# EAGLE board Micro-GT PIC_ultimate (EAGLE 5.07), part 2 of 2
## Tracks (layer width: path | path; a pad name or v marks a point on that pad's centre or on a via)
0V  (via drill 0.61)
  Top 0.254: X2.5 46.99,12.7 | 158.75,81.28 X3.2 | 153.67,62.23 153.67,64.77 | 64.77,11.43 X2.G1
  Top 0.508: 91.44,144.78 IC6.8
  Top 0.559: 43.18,27.94 46.99,31.75
  Top 0.61: C13.2 C14.2 86.36,82.55 R66.1 R67.1 88.9,106.68 96.52,106.68 R60.1 | R65.1 91.44,125.73 R63.1 | 92.71,127 R63.1 | R64.1 92.71,127 | R63.1 R61.1 | 92.71,127 92.71,143.51 91.44,144.78 | C3.2 6.35,88.9 6.35,63.5 | IC2.15 55.88,29.21 57.15,29.21 | 59.69,29.21 60.96,29.21 IC4.5 | 59.69,29.21 57.15,29.21 | IC4.14 57.15,38.1 57.15,29.21 | 59.69,29.21 59.69,11.43 55.88,7.62 45.72,7.62 45.72,10.16 | 45.72,10.16 45.72,11.43 46.99,12.7 | R34.2 33.02,29.21 D1.A 31.75,26.67 C12.- 31.75,15.24 IC3.GND | Q6.1 38.1,34.29 38.1,24.13 39.37,22.86 | 39.37,22.86 C2.- | 46.99,31.75 ZX1.31 | 39.37,22.86 39.37,24.13 43.18,27.94 43.18,10.16 45.72,10.16 | v20.32,24.13 20.32,21.59 D3.C | SV26.3 119.38,3.81 R55.A | 153.67,81.28 153.67,62.23 Q4.1
  Top 0.813: R53.1 R52.1 83.82,106.68 R66.1 | ICSP2.3 ICSP1.3 | R54.1 R68.1 | 6.35,63.5 7.62,62.23 SV25.1 DVPP.K DPGC.K | IC1.8 128.27,35.56 120.65,35.56
  Top 1.016: C9.- 8.89,16.51 C1.2 C11.2 C10.2 GND.TP DPGD.K | IC3.GND 29.21,5.08 -.1 | IC1.5 120.65,35.56 120.65,34.29 118.11,34.29 118.11,19.05 R55.A | AN7.1 AN6.1 | AN1.1 AN2.1 AN3.1 AN4.1 | IC4.8 IC4.9 | Q10.E 138.43,151.13 138.43,135.89 139.7,134.62 139.7,129.54 IC7.4 | Q2.1 134.62,19.05
  Top 1.143: AN0.1 76.2,3.81 C7.+
  Top 1.27: SV2.5 SV7.1 | SV7.5 SV8.1 | R56.1 134.62,19.05 R51.1 R57.A | v64.77,3.81 64.77,11.43
  Top 1.676: R77.1 D15.A
  Top 1.778: R78.1 R77.1 120.65,128.27 120.65,134.62 114.3,143.51 Q12.E | AVANTI.K INDIETRO.K 153.67,138.43 153.67,127 158.75,127 X7.2
  Top 2.54: 158.75,81.28 153.67,81.28 153.67,88.9 D8.A D9.A D10.A D11.A 146.05,115.57 D14.A
  Bottom 0.254: 46.99,12.7 X2.5 | 158.75,127 X7.2
  Bottom 0.508: D3.C 26.67,22.86 31.75,22.86 | 31.75,22.86 C12.- | 31.75,22.86 38.1,22.86 C2.-
  Bottom 0.61: R66.1 86.36,106.68 77.47,106.68 RESET.3 | R61.1 R62.1 | C11.2 15.24,24.13 ICSP2.3 v20.32,24.13 | 46.99,12.7 48.26,11.43 X2.G1 | SV26.20 161.29,5.08 154.94,6.35 153.67,8.89 153.67,15.24 148.59,16.51 R57.A | SV26.3 116.84,5.08 110.49,5.08 AN7.1 | Q3.1 Q2.1 Q1.1 152.4,57.15 152.4,59.69 Q4.1 | POWER.K 2.54,11.43 2.54,16.51 C9.-
  Bottom 0.813: R64.1 R60.1 121.92,127 R77.1 | DPGC.K 8.89,40.64 R68.1 | DPGD.K 10.16,38.1 R54.1 | C3.2 5.08,86.36 11.43,86.36 C4.2 | R38.1 8.89,55.88 SV25.1 | IC7.4 137.16,125.73 R78.1
  Bottom 1.016: AN1.1 AN0.1 | AN4.1 AN5.1 AN6.1 | C7.+ 76.2,30.48 69.85,30.48 IC4.8
  Bottom 1.143: AN0.1 v64.77,3.81
  Bottom 1.27: SV1.1 13.97,154.94 26.67,154.94 | 26.67,152.4 SV2.1 | 26.67,152.4 SV1.5 | 54.61,154.94 39.37,154.94 | 26.67,154.94 26.67,152.4 | 39.37,154.94 26.67,154.94 | 39.37,154.94 SV2.5 | 74.93,154.94 R59.1 | 74.93,154.94 68.58,154.94 | IC6.8 91.44,154.94 74.93,154.94 | 54.61,154.94 SV7.5 | 68.58,154.94 54.61,154.94 | 68.58,154.94 SV8.5 | S13.1 S13.2 S13.3 81.28,26.67 C7.+ | R56.1 128.27,15.24 121.92,15.24 R55.A
  Bottom 1.778: 149.86,127 D14.A | IC7.4 149.86,127 | 149.86,127 158.75,127
+5V  (via drill 0.61)
  Top 0.406: 81.28,118.11 78.74,115.57
  Top 0.559: 48.26,68.58 49.53,69.85
  Top 0.61: SV1.3 R12.2 v19.05,147.32 | SV2.3 33.02,151.13 v33.02,147.32 33.02,146.05 34.29,144.78 41.91,144.78 49.53,149.86 | 49.53,149.86 SV7.3 | v63.5,146.05 R42.2 | JP4.1 73.66,100.33 73.66,104.14 74.93,106.68 78.74,110.49 78.74,115.57 | 81.28,118.11 81.28,135.89 82.55,137.16 S10.3 | S10.4 v80.01,144.78 | v52.07,149.86 49.53,149.86 | R55.E 121.92,16.51 121.92,3.81 SV26.4 | C1.1 2.54,21.59 2.54,52.07 SV25.2 | 49.53,69.85 ZX1.32 | v48.26,50.8 48.26,68.58 | v55.88,50.8 55.88,41.91 54.61,40.64 54.61,30.48 IC2.16 48.26,24.13 48.26,20.32 46.99,19.05 C6.- v45.72,15.24 | AN0.3 v73.66,16.51 | v139.7,140.97 139.7,137.16 140.97,135.89 140.97,125.73 139.7,124.46 139.7,85.09 146.05,85.09 146.05,62.23 147.32,60.96 147.32,38.1 142.24,35.56 JP7.2 | IC1.16 111.76,41.91 v113.03,41.91 | IC1.3 v115.57,41.91
  Top 1.016: R55.E 127,22.86 JP6.1 | IC1.4 IC1.3 | AN7.3 AN6.3
  Top 1.27: R42.2 SV8.3
  Bottom 0.406: 24.13,25.4 21.59,22.86 | v73.66,16.51 50.8,16.51 48.26,19.05 C6.-
  Bottom 0.61: v33.02,147.32 v19.05,147.32 | IC6.9 92.71,144.78 v80.01,144.78 69.85,144.78 v63.5,146.05 59.69,146.05 55.88,149.86 v52.07,149.86 | S10.3 S10.4 | JP7.2 140.97,34.29 128.27,34.29 127,35.56 124.46,35.56 | 124.46,35.56 118.11,35.56 IC1.4 | 124.46,35.56 JP6.1 | SV26.4 120.65,5.08 114.3,8.89 AN7.3 | v55.88,50.8 v48.26,50.8 | C1.1 6.35,22.86 21.59,22.86 | 24.13,25.4 41.91,25.4 44.45,27.94 49.53,27.94 IC2.16 | v115.57,41.91 v113.03,41.91
  Bottom 0.813: v139.7,140.97 S10.3
  Bottom 1.016: AN0.3 AN1.3 AN2.3 AN3.3 AN4.3 AN5.3 AN6.3
  Bottom 1.27: IC3.OUT 34.29,15.24 v45.72,15.24
+12V
  Top 0.61: C12.+ 29.21,17.78 26.67,17.78 | 26.67,17.78 IC3.IN | 26.67,17.78 26.67,27.94 24.13,29.21 Q7.E | R79.2 10.16,41.91 R35.2
  Bottom 0.61: C11.1 5.08,24.13 5.08,31.75 6.35,34.29 | 6.35,34.29 6.35,43.18 R35.2 | 6.35,34.29 Q7.E
  Bottom 1.27: IC3.IN 26.67,15.24 20.32,15.24 IC5.OUT
N$1  (via drill 0.61)
  Top 0.813: v137.16,54.61 137.16,58.42 Q2.2
  Bottom 0.61: R9.1 v137.16,54.61
N$2
  Top 0.61: R10.2 106.68,35.56 114.3,35.56 114.3,58.42 Q3.2
N$3  (via drill 0.61)
  Top 0.61: DIS1.5 139.7,55.88 v142.24,55.88
  Bottom 0.61: v142.24,55.88 153.67,55.88 R17.2
N$4
  Top 0.61: POWER.A R79.1
N$5
  Top 1.016: IC1.13 R1.1
N$6
  Top 1.016: IC1.12 R2.1
N$7
  Top 1.016: IC1.11 R3.1
N$8
  Top 1.016: IC1.10 R4.1
N$9
  Top 1.016: IC1.9 R5.1
N$10
  Bottom 0.61: IC1.15 113.03,49.53 120.65,49.53 123.19,52.07 143.51,52.07 144.78,50.8 151.13,50.8 R6.1
N$11
  Top 1.016: IC1.14 R7.1
N$12
  Bottom 0.61: Q1.2 R8.2
N$13  (via drill 0.61)
  Top 0.61: v124.46,50.8 DIS2.5
  Bottom 0.61: R18.2 135.89,50.8 v124.46,50.8
N$14  (via drill 0.61)
  Top 0.61: DIS3.5 110.49,63.5 v110.49,53.34
  Bottom 0.61: v110.49,53.34 144.78,53.34 R19.2
N$15  (via drill 0.61)
  Top 0.813: v148.59,48.26 148.59,60.96 DIS4.5
  Bottom 0.813: R20.2 v148.59,48.26
N$16  (via drill 0.61)
  Top 0.61: v116.84,72.39 DIS2.9
  Top 1.016: DIS4.9 142.24,82.55 129.54,82.55 DIS1.9 v129.54,73.66
  Bottom 0.61: DIS3.9 111.76,72.39 v116.84,72.39 118.11,73.66 v129.54,73.66 | R6.2 161.29,66.04 161.29,83.82 142.24,83.82 DIS4.9
N$17  (via drill 0.61)
  Top 0.61: R1.2 v118.11,76.2 | v134.62,76.2 DIS1.7
  Bottom 0.254: v118.11,76.2 121.92,76.2
  Bottom 0.61: 121.92,76.2 DIS2.7 | DIS3.7 113.03,76.2 v118.11,76.2 v134.62,76.2 152.4,76.2 152.4,82.55 147.32,82.55 DIS4.7
N$18
  Top 0.61: R2.2 120.65,76.2 118.11,78.74 118.11,82.55 | 118.11,82.55 124.46,82.55 DIS2.6 | DIS3.6 111.76,82.55 118.11,82.55
  Bottom 0.61: 137.16,77.47 DIS1.6 | 137.16,77.47 124.46,77.47 DIS2.6 | DIS4.6 149.86,77.47 137.16,77.47
N$19
  Top 0.61: R3.2 121.92,59.69 DIS2.4
  Bottom 0.61: DIS3.4 109.22,62.23 121.92,62.23 | 121.92,62.23 DIS2.4 | 134.62,62.23 DIS1.4 | 121.92,62.23 134.62,62.23 | DIS4.4 147.32,62.23 134.62,62.23
N$20  (via drill 0.61)
  Top 0.61: v104.14,60.96 DIS3.2 | v116.84,60.96 DIS2.2 | R4.2 125.73,57.15 129.54,57.15 DIS1.2 v129.54,68.58
  Bottom 0.61: v104.14,60.96 v116.84,60.96 123.19,60.96 R4.2 | DIS4.2 142.24,68.58 v129.54,68.58
N$21
  Top 0.61: DIS1.1 128.27,63.5 R5.2
  Bottom 0.61: DIS3.1 101.6,67.31 114.3,67.31 | 114.3,67.31 DIS2.1 | DIS4.1 139.7,67.31 127,67.31 | 114.3,67.31 127,67.31 | 127,67.31 DIS1.1
N$22
  Top 0.61: R7.2 115.57,78.74 DIS2.10
  Bottom 1.016: DIS3.10 101.6,82.55 114.3,82.55 | DIS2.10 114.3,82.55 | 127,82.55 DIS1.10 | 114.3,82.55 127,82.55 | DIS4.10 139.7,82.55 127,82.55
N$23  (via drill 0.61)
  Top 0.61: v93.98,88.9 97.79,85.09 97.79,59.69 SV19.1 | IC1.7 119.38,44.45 v119.38,55.88
  Bottom 0.406: IC1.7 128.27,35.56 142.24,35.56 143.51,34.29 143.51,29.21 R51.2
  Bottom 0.61: S26.16 68.58,95.25 87.63,95.25 v93.98,88.9 | v119.38,55.88 110.49,55.88 106.68,58.42 SV19.1
N$24  (via drill 0.61)
  Top 0.61: S13.6 93.98,26.67 v93.98,53.34 | v81.28,58.42 78.74,60.96 v78.74,67.31
  Bottom 0.61: v93.98,53.34 93.98,58.42 v81.28,58.42 | v78.74,67.31 RN1.1
N$25
  Top 1.27: D2.A 17.78,15.24 IC5.GND
N$26  (via drill 0.61)
  Top 0.61: R52.2 v83.82,96.52 | IC1.1 107.95,40.64 v107.95,55.88 107.95,83.82 106.68,86.36 106.68,95.25 v104.14,95.25
  Bottom 0.61: S26.15 64.77,99.06 69.85,99.06 72.39,96.52 v83.82,96.52 | v107.95,55.88 SV19.2 | R52.2 92.71,95.25 v104.14,95.25
N$27  (via drill 0.61)
  Top 0.813: v144.78,73.66 DIS4.8
  Bottom 0.813: Q4.3 146.05,73.66 v144.78,73.66
N$28
  Top 0.254: S2.3 15.24,130.81
  Top 0.61: SV1.4 20.32,151.13 20.32,135.89 17.78,133.35 15.24,133.35 15.24,130.81
  Bottom 0.254: S1.3 7.62,130.81 | 15.24,130.81 S2.3 | 22.86,130.81 S3.3 | 30.48,130.81 S4.3
  Bottom 0.559: 7.62,130.81 8.89,132.08 13.97,132.08 | 13.97,132.08 15.24,130.81 | 21.59,132.08 22.86,130.81 | 13.97,132.08 21.59,132.08 | 30.48,130.81 30.48,132.08 21.59,132.08
N$29
  Top 0.61: S13.4 90.17,22.86 95.25,22.86 RN2.1
N$30  (via drill 0.61)
  Top 0.61: RN3.9 53.34,46.99 v53.34,59.69 | v29.21,60.96 29.21,50.8 RC0.K
  Bottom 0.61: v53.34,59.69 52.07,60.96 v29.21,60.96
N$31  (via drill 0.61)
  Top 0.61: v39.37,50.8 v40.64,45.72
  Bottom 0.61: RC1.K v39.37,50.8 | v40.64,45.72 44.45,45.72 49.53,40.64 RN3.8
N$32
  Bottom 0.61: RC2.K 46.99,45.72 52.07,45.72 RN3.7
N$33
  Top 0.813: R11.2 158.75,63.5 Q4.2
N$34  (via drill 0.61)
  Top 0.61: v24.13,59.69 RB7.K | v62.23,13.97 63.5,15.24 67.31,15.24 v67.31,13.97 | v77.47,13.97 77.47,41.91 RN2.9
  Bottom 0.406: v67.31,13.97 v77.47,13.97
  Bottom 0.61: v24.13,59.69 22.86,60.96 1.27,60.96 1.27,19.05 11.43,19.05 12.7,16.51 46.99,16.51 49.53,13.97 v62.23,13.97
N$35
  Top 0.61: IC2.11 IC4.6
  Bottom 0.61: SV11.2 76.2,31.75 72.39,31.75 69.85,34.29 67.31,34.29 67.31,29.21 63.5,29.21 IC4.6
N$36  (via drill 0.61)
  Top 0.61: IC1.2 109.22,41.91 v109.22,53.34 | v105.41,93.98 105.41,59.69 104.14,58.42 v104.14,53.34
  Bottom 0.61: S26.14 62.23,100.33 72.39,100.33 77.47,102.87 80.01,102.87 R53.2 91.44,93.98 v105.41,93.98 | SV19.3 v104.14,53.34 v109.22,53.34
N$37  (via drill 0.61)
  Top 0.559: 60.96,87.63 v60.96,91.44
  Top 0.61: IC1.6 116.84,44.45 v116.84,50.8 | v50.8,34.29 52.07,34.29 52.07,40.64 53.34,41.91 53.34,44.45 54.61,45.72 54.61,62.23 58.42,66.04 58.42,85.09 60.96,87.63 | v60.96,91.44 60.96,95.25 S26.13 | v102.87,50.8 102.87,58.42 100.33,62.23 v100.33,87.63
  Bottom 0.406: R54.2 22.86,36.83 26.67,36.83 27.94,35.56 29.21,36.83 31.75,34.29 v50.8,34.29
  Bottom 0.61: SV19.4 v102.87,50.8 v116.84,50.8 | v100.33,87.63 76.2,87.63 72.39,91.44 v60.96,91.44
N$38
  Top 0.254: 10.16,137.16 S2.2 10.16,135.89
  Top 0.61: R14.1 10.16,138.43 10.16,137.16 | 10.16,135.89 5.08,130.81 SV30.7
  Bottom 0.559: 25.4,111.76 S11.7
  Bottom 0.61: SV30.7 5.08,111.76 25.4,111.76
N$39  (via drill 0.61)
  Top 0.559: v20.32,95.25 20.32,82.55
  Top 0.61: v39.37,83.82 ZX1.13 | 20.32,82.55 v24.13,82.55 | v20.32,95.25 JP1.2
  Bottom 0.61: v39.37,83.82 38.1,82.55 v24.13,82.55 | JP8.2 1.27,102.87 1.27,96.52 3.81,96.52 5.08,95.25 7.62,95.25 8.89,96.52 12.7,96.52 13.97,95.25 v20.32,95.25
N$40
  Top 0.254: 2.54,137.16 S1.2 2.54,135.89 | 2.54,130.81 S1.1 2.54,129.54
  Top 0.61: R13.1 2.54,139.7 2.54,137.16 | 2.54,130.81 2.54,135.89 | 2.54,129.54 1.27,128.27 1.27,109.22 SV30.8
  Bottom 0.61: SV30.8 2.54,114.3 S11.8
N$41  (via drill 0.61)
  Top 1.016: v36.83,96.52 ZX1.14 | JP2.2 v15.24,96.52
  Bottom 1.016: v15.24,96.52 v36.83,96.52 | JP9.1 JP2.2
N$42  (via drill 0.61)
  Top 0.61: ZX1.9 49.53,93.98 46.99,96.52 46.99,97.79 44.45,102.87 v44.45,104.14 | v5.08,97.79 5.08,91.44 3.81,90.17 3.81,80.01 SV5.2 SV24.2
  Bottom 0.406: v44.45,104.14 25.4,104.14 22.86,101.6 19.05,101.6 16.51,99.06
  Bottom 0.61: 16.51,99.06 6.35,99.06 v5.08,97.79
N$43  (via drill 0.61)
  Top 0.61: v31.75,133.35 31.75,116.84 33.02,115.57 S11.5
  Bottom 0.254: 25.4,137.16 S4.2 25.4,135.89
  Bottom 0.559: 10.16,106.68 SV30.5 | 27.94,109.22 S11.5
  Bottom 0.61: R16.1 16.51,140.97 24.13,140.97 25.4,138.43 25.4,137.16 | 10.16,106.68 22.86,106.68 22.86,109.22 27.94,109.22 | 25.4,135.89 27.94,133.35 v31.75,133.35
N$44  (via drill 0.61)
  Top 0.61: v74.93,58.42 77.47,55.88 RN2.8
  Bottom 0.406: RB6.K 38.1,55.88 39.37,57.15 54.61,57.15 55.88,58.42 v74.93,58.42
N$45  (via drill 0.61)
  Top 0.61: Q5.2 C4.1 v8.89,64.77
  Top 0.813: JP9.2 6.35,101.6 6.35,96.52 Q5.2
  Bottom 0.61: SV6.1 2.54,64.77 v8.89,64.77
N$46
  Top 0.61: Q5.1 2.54,92.71 C3.1 SV5.1
  Top 0.813: Q5.1 JP8.1
N$47  (via drill 0.61)
  Top 0.61: v72.39,85.09 v72.39,101.6 | v52.07,100.33 S26.10
  Top 0.813: v147.32,69.85 152.4,69.85 152.4,49.53 R8.1
  Bottom 0.61: v72.39,85.09 73.66,83.82 82.55,83.82 86.36,80.01 97.79,80.01 107.95,69.85 v147.32,69.85 | R8.1 149.86,49.53 142.24,49.53 135.89,43.18 107.95,43.18 106.68,41.91 102.87,41.91 SV20.2 | v52.07,100.33 53.34,101.6 v72.39,101.6
N$48
  Bottom 0.61: RC3.K RN3.6
N$49
  Top 0.61: RN3.5 RC4.K
N$50  (via drill 0.61)
  Top 0.559: v53.34,86.36 53.34,109.22
  Top 0.61: S26.9 49.53,101.6 50.8,102.87 50.8,109.22 53.34,109.22 | v99.06,86.36 99.06,60.96 101.6,58.42 101.6,48.26 102.87,45.72 102.87,39.37 SV20.1
  Bottom 0.61: v53.34,86.36 54.61,85.09 62.23,85.09 63.5,86.36 v99.06,86.36 | R11.1 157.48,46.99 144.78,46.99 138.43,40.64 104.14,40.64 SV20.1
N$51
  Top 0.61: S25.8 158.75,36.83 157.48,36.83 157.48,46.99 R17.1
N$52
  Bottom 0.406: R18.1 140.97,38.1 143.51,35.56 153.67,35.56 S25.7
N$53
  Top 0.813: Q1.3 140.97,62.23 140.97,72.39 132.08,72.39 DIS1.8
N$54  (via drill 0.61)
  Top 0.813: v127,60.96 125.73,62.23 125.73,73.66 DIS2.8
  Bottom 0.813: Q2.3 133.35,60.96 v127,60.96
N$55  (via drill 0.61)
  Top 0.61: Q3.3 113.03,60.96 v113.03,73.66
  Bottom 0.61: v113.03,73.66 DIS3.8
N$56
  Top 0.61: RN3.4 RC5.K
N$57  (via drill 0.61)
  Top 0.813: S25.6 153.67,35.56 148.59,38.1 v148.59,39.37
  Bottom 0.813: v148.59,39.37 R19.1
N$58
  Bottom 0.61: R20.1 144.78,36.83 157.48,36.83 157.48,30.48 153.67,30.48 S25.5
N$59
  Top 0.61: R21.2 R22.2 R23.2 R24.2 SV2.2
N$60  (via drill 0.61)
  Top 0.254: 53.34,130.81 S7.3
  Top 0.61: SV2.4 35.56,151.13 JP3.2 | v55.88,133.35 54.61,132.08 | 54.61,132.08 53.34,130.81 | 54.61,132.08 v54.61,146.05
  Bottom 0.254: S5.3 38.1,129.54 | 45.72,129.54 S6.3 45.72,130.81 | 60.96,130.81 S8.3
  Bottom 0.457: 58.42,133.35 60.96,130.81
  Bottom 0.559: 45.72,130.81 48.26,133.35
  Bottom 0.61: 38.1,129.54 39.37,127 45.72,128.27 45.72,129.54 | 58.42,133.35 v55.88,133.35 48.26,133.35 | v54.61,146.05 JP3.2
N$61  (via drill 0.61)
  Top 0.254: S5.1 33.02,129.54 | S5.2 33.02,135.89
  Top 0.61: 33.02,143.51 JP3.1 | 33.02,143.51 33.02,137.16 S5.2 | S11.4 35.56,127 33.02,129.54 | 33.02,135.89 33.02,130.81 S5.1 | SV30.4 v12.7,133.35 | 33.02,143.51 30.48,144.78 21.59,144.78 R21.1
  Bottom 0.61: v12.7,133.35 17.78,133.35 20.32,135.89 20.32,139.7 R21.1
N$62  (via drill 0.61)
  Top 0.61: S11.3 36.83,113.03 v36.83,99.06 | v17.78,99.06 17.78,106.68 SV30.3 15.24,115.57 16.51,116.84 16.51,132.08 20.32,132.08 22.86,134.62 27.94,134.62 27.94,138.43 R22.1 v29.21,142.24 | v40.64,142.24 40.64,137.16 S6.2
  Bottom 0.61: v17.78,99.06 v36.83,99.06 | v29.21,142.24 v40.64,142.24
N$63  (via drill 0.61)
  Top 0.559: 39.37,123.19 43.18,119.38
  Top 0.61: v17.78,115.57 SV30.2 | v8.89,115.57 8.89,132.08 12.7,135.89 v12.7,140.97 | S11.2 43.18,116.84 43.18,119.38 | 39.37,123.19 v39.37,132.08 35.56,135.89 v35.56,140.97
  Bottom 0.254: 48.26,135.89 S7.2
  Bottom 0.559: 48.26,134.62 45.72,132.08 v39.37,132.08
  Bottom 0.61: v12.7,140.97 12.7,142.24 26.67,142.24 27.94,140.97 | 27.94,140.97 R23.1 | 27.94,140.97 v35.56,140.97 | 48.26,134.62 48.26,135.89
  Bottom 0.813: v8.89,115.57 v17.78,115.57
N$64  (via drill 0.61)
  Top 0.406: 22.86,102.87 21.59,104.14
  Top 0.508: 48.26,111.76 v46.99,113.03
  Top 0.559: 27.94,130.81 31.75,134.62
  Top 0.61: 27.94,130.81 27.94,124.46 24.13,120.65 24.13,115.57 20.32,115.57 SV30.1 21.59,109.22 21.59,104.14 | 31.75,134.62 R24.1 | v48.26,99.06 48.26,111.76 | v22.86,95.25 22.86,102.87 | v55.88,140.97 55.88,137.16 S8.2
  Bottom 0.61: S11.1 44.45,113.03 v46.99,113.03 | v48.26,99.06 46.99,97.79 40.64,97.79 38.1,95.25 v22.86,95.25 | v55.88,140.97 38.1,140.97 36.83,139.7 R24.1
N$65  (via drill 0.61)
  Top 0.61: v49.53,59.69 50.8,60.96 50.8,64.77 49.53,66.04 RN1.9
  Bottom 0.61: RD0.K 27.94,59.69 v49.53,59.69
N$66
  Top 0.61: R13.2 R14.2 R15.2 R16.2 SV1.2
N$67  (via drill 0.61)
  Top 0.61: R15.1 13.97,140.97 17.78,140.97 17.78,137.16 S3.2 | v22.86,113.03 v22.86,110.49
  Bottom 0.254: 17.78,135.89 S3.2
  Bottom 0.508: 5.08,134.62 16.51,134.62
  Bottom 0.559: 26.67,110.49 S11.6
  Bottom 0.61: 3.81,106.68 7.62,106.68 SV30.6 | 3.81,106.68 1.27,106.68 1.27,121.92 5.08,121.92 5.08,134.62 | 16.51,134.62 17.78,135.89 | v22.86,110.49 26.67,110.49 | v22.86,113.03 3.81,113.03 3.81,106.68
N$68  (via drill 0.61)
  Top 0.559: 5.08,71.12 SV24.1
  Top 0.61: SV6.2 5.08,71.12
  Top 0.813: v46.99,85.09 ZX1.10
  Bottom 0.61: v46.99,85.09 6.35,85.09 6.35,76.2 8.89,76.2 8.89,66.04 5.08,66.04 SV6.2
N$69  (via drill 0.61)
  Top 0.254: S15.1 2.54,119.38 | 2.54,124.46 S15.2
  Top 0.406: SV29.1 67.31,116.84 66.04,115.57 66.04,111.76 69.85,111.76 69.85,116.84 71.12,118.11 71.12,133.35 69.85,134.62 v69.85,143.51
  Top 0.61: S12.16 52.07,111.76 55.88,111.76 55.88,115.57 58.42,118.11 v58.42,120.65 | 48.26,144.78 41.91,142.24 R25.1 | v48.26,147.32 48.26,144.78 | 2.54,119.38 2.54,124.46 | 48.26,144.78 v50.8,143.51
  Bottom 0.254: S15.2 2.54,125.73
  Bottom 0.61: v58.42,120.65 66.04,120.65 SV29.1 | v48.26,147.32 38.1,147.32 36.83,148.59 1.27,148.59 1.27,125.73 2.54,125.73 | v50.8,143.51 v69.85,143.51
N$70  (via drill 0.61)
  Top 0.61: v60.96,110.49 S12.13 | v74.93,115.57 SV29.4 76.2,120.65 v76.2,138.43
  Bottom 0.254: S18.2 25.4,124.46
  Bottom 0.559: 46.99,134.62 44.45,134.62 43.18,133.35 34.29,133.35 31.75,132.08
  Bottom 0.61: v60.96,110.49 60.96,109.22 74.93,109.22 v74.93,115.57 | 46.99,134.62 R28.1 55.88,139.7 57.15,138.43 59.69,138.43 59.69,140.97 69.85,140.97 71.12,138.43 v76.2,138.43 | 31.75,132.08 31.75,128.27 26.67,127 25.4,124.46
N$71  (via drill 0.61)
  Top 1.016: R30.2 v60.96,147.32
  Top 1.27: R32.2 R31.2 | R29.2 R30.2 SV8.2
  Bottom 1.016: R32.2 68.58,147.32 v60.96,147.32
N$72  (via drill 0.61)
  Top 0.61: SV8.4 64.77,151.13 64.77,147.32 71.12,147.32 71.12,137.16 73.66,134.62 v73.66,115.57
  Bottom 0.254: S19.3 38.1,119.38 | 45.72,119.38 S20.3
  Bottom 0.457: 66.04,118.11 68.58,115.57 | 57.15,120.65 58.42,119.38
  Bottom 0.559: 39.37,120.65 44.45,120.65 53.34,120.65 57.15,120.65
  Bottom 0.61: 38.1,119.38 39.37,120.65 | 44.45,120.65 45.72,119.38 | 68.58,115.57 v73.66,115.57 | 66.04,118.11 60.96,118.11 S22.3 60.96,119.38 58.42,119.38 | 53.34,120.65 S21.3
N$73  (via drill 0.61)
  Top 0.508: 54.61,147.32 55.88,146.05
  Top 0.61: v73.66,110.49 74.93,111.76 74.93,113.03 77.47,115.57 SV29.5 | R29.1 55.88,143.51 55.88,146.05 | 54.61,147.32 53.34,147.32 53.34,139.7 50.8,137.16 v50.8,121.92 | v45.72,114.3 43.18,111.76 39.37,111.76 v39.37,121.92
  Bottom 0.254: 33.02,124.46 S19.2 | S19.1 33.02,119.38
  Bottom 0.406: v73.66,110.49 66.04,110.49 63.5,113.03 63.5,115.57 62.23,116.84 S12.12 57.15,116.84 55.88,115.57 54.61,116.84 53.34,115.57 52.07,116.84 49.53,116.84 46.99,114.3 v45.72,114.3
  Bottom 0.61: 33.02,121.92 v39.37,121.92 v50.8,121.92 | 33.02,121.92 33.02,124.46 | 33.02,119.38 33.02,121.92
N$74  (via drill 0.61)
  Top 0.254: 40.64,124.46 S20.2
  Top 0.61: S12.11 62.23,110.49 71.12,110.49 v71.12,116.84 | v80.01,124.46 SV29.6 | 40.64,124.46 41.91,123.19 v43.18,123.19
  Bottom 0.457: SV29.6 77.47,116.84
  Bottom 0.559: 72.39,130.81 62.23,138.43 62.23,139.7 R30.1 | v43.18,123.19 62.23,123.19
  Bottom 0.61: 77.47,116.84 v71.12,116.84 | 72.39,130.81 76.2,130.81 80.01,128.27 v80.01,124.46 63.5,124.46 62.23,123.19
N$75  (via drill 0.61)
  Top 0.61: S12.10 v64.77,123.19 v64.77,133.35 64.77,138.43 R31.1 | v82.55,123.19 SV29.7 | v58.42,132.08 v59.69,133.35
  Bottom 0.254: S21.2 48.26,125.73
  Bottom 0.559: 50.8,132.08 v58.42,132.08
  Bottom 0.61: v64.77,123.19 v82.55,123.19 | 48.26,125.73 50.8,128.27 50.8,132.08 | v59.69,133.35 v64.77,133.35
N$76  (via drill 0.61)
  Top 0.254: 55.88,124.46 S22.2
  Top 0.61: S12.9 68.58,115.57 v68.58,121.92 R32.1 | v55.88,121.92 55.88,124.46
  Bottom 0.61: SV29.8 82.55,121.92 v68.58,121.92 v55.88,121.92
N$77
  Top 1.27: R26.2 R25.2 R27.2 R28.2 SV7.2
N$78  (via drill 0.61)
  Top 0.406: v45.72,109.22 45.72,113.03 50.8,118.11
  Top 0.559: 45.72,121.92 43.18,124.46
  Top 0.61: R26.1 39.37,134.62 40.64,133.35 43.18,133.35 | 43.18,124.46 43.18,133.35 | 45.72,121.92 50.8,120.65 50.8,118.11 50.8,115.57 S12.15 | v69.85,129.54 SV29.2 | 43.18,133.35 48.26,133.35 v49.53,134.62 | v26.67,121.92 27.94,120.65 27.94,116.84 29.21,115.57 29.21,109.22 v35.56,109.22
  Bottom 0.254: S16.2 10.16,124.46
  Bottom 0.559: v69.85,129.54 66.04,132.08 66.04,134.62 v49.53,134.62
  Bottom 0.61: v35.56,109.22 v45.72,109.22
  Bottom 0.813: 10.16,124.46 12.7,121.92 v26.67,121.92
N$79  (via drill 0.61)
  Top 0.61: S12.14 54.61,127 58.42,128.27 | 58.42,128.27 57.15,132.08 57.15,134.62 58.42,135.89 58.42,137.16 59.69,138.43 59.69,143.51 54.61,148.59 52.07,148.59 52.07,140.97 44.45,140.97 R27.1 | v72.39,125.73 SV29.3 | 58.42,128.27 v62.23,127 | v29.21,134.62 29.21,133.35 22.86,133.35 20.32,130.81 20.32,128.27 17.78,125.73 S17.2
  Bottom 0.559: 64.77,125.73 v72.39,125.73 | v29.21,134.62 41.91,134.62 43.18,135.89
  Bottom 0.61: v62.23,127 64.77,125.73 | 43.18,135.89 43.18,139.7 R27.1
N$80  (via drill 0.61)
  Top 0.508: 53.34,71.12 54.61,69.85 RN1.8
  Top 0.61: v38.1,62.23 v38.1,69.85 | v48.26,69.85 v48.26,85.09 | v50.8,85.09 53.34,82.55 53.34,71.12
  Bottom 0.61: RD1.K v38.1,62.23 | v38.1,69.85 v48.26,69.85 | v48.26,85.09 v50.8,85.09
N$81  (via drill 0.61)
  Top 0.559: v43.18,83.82 SV16.1
  Top 0.61: v67.31,85.09 ZX1.2
  Top 1.016: SV16.1 S11.16
  Bottom 0.61: v67.31,85.09 66.04,83.82 v43.18,83.82
N$82  (via drill 0.61)
  Top 0.559: 40.64,81.28 40.64,97.79
  Top 0.61: ZX1.3 64.77,83.82 59.69,83.82 v59.69,81.28 | 40.64,81.28 v44.45,81.28 | 40.64,97.79 41.91,99.06 41.91,100.33 SV16.2
  Top 1.016: SV16.2 S11.15
  Bottom 0.61: v44.45,81.28 v59.69,81.28
N$83  (via drill 0.61)
  Top 0.559: v35.56,80.01 v35.56,97.79
  Top 0.61: v55.88,80.01 v55.88,86.36
  Top 1.016: SV16.3 S11.14
  Bottom 0.406: v35.56,97.79 39.37,97.79 39.37,101.6 SV16.3
  Bottom 0.61: ZX1.4 60.96,86.36 v55.88,86.36 | v35.56,80.01 v55.88,80.01
N$84  (via drill 0.61)
  Top 0.61: ZX1.5 59.69,92.71 58.42,93.98 v58.42,109.22 | v45.72,107.95 41.91,109.22 39.37,109.22 39.37,100.33 v38.1,99.06
  Top 1.016: SV16.4 S11.13
  Bottom 0.406: SV16.4 v38.1,99.06
  Bottom 0.61: v58.42,109.22 49.53,109.22 v45.72,107.95
N$85  (via drill 0.61)
  Top 0.61: v46.99,111.76 v46.99,100.33
  Bottom 0.61: S11.12 33.02,111.76 v46.99,111.76 | v46.99,100.33 50.8,100.33 50.8,93.98 52.07,91.44 54.61,91.44 ZX1.6
N$86  (via drill 0.61)
  Top 0.559: 33.02,86.36 SV16.5
  Top 0.61: v34.29,86.36 33.02,86.36
  Top 1.016: SV16.5 S11.11
  Bottom 0.406: 52.07,86.36 ZX1.7
  Bottom 0.61: v34.29,86.36 52.07,86.36
N$87  (via drill 0.61)
  Top 0.254: 72.39,111.76 RESET.2
  Top 0.61: ZX1.1 71.12,90.17 71.12,104.14 72.39,105.41 RESET.1 72.39,106.68 72.39,111.76 | v19.05,143.51 R12.1 | v63.5,144.78 67.31,144.78 67.31,134.62 66.04,133.35 v66.04,116.84
  Bottom 0.254: RESET.2 72.39,111.76
  Bottom 0.61: v19.05,143.51 19.05,144.78 v63.5,144.78 | v66.04,116.84 66.04,111.76 72.39,111.76
N$88  (via drill 0.61)
  Top 0.61: RD2.K v44.45,66.04
  Bottom 0.406: v44.45,66.04 46.99,68.58 48.26,68.58 49.53,69.85 52.07,69.85 RN1.7
N$89
  Bottom 0.406: RD3.K RN1.6
N$90  (via drill 0.61)
  Top 0.61: S11.10 25.4,109.22 24.13,109.22 v24.13,104.14
  Bottom 0.406: v24.13,104.14 22.86,102.87 JP1.1
N$91  (via drill 0.6, 0.61)
  Top 0.406: v15.24,105.41 JP2.1
  Top 0.813: JP2.1 v15.24,105.41
  Bottom 0.813: S11.9 25.4,105.41 v15.24,105.41
  other vias: 25.4,106.68
N$92
  Top 0.61: RD4.K RN1.5
N$93
  Bottom 0.61: RD5.K RN1.4
N$94  (via drill 0.61)
  Top 0.61: v74.93,64.77 RD6.K
  Bottom 0.61: RN1.3 67.31,64.77 v74.93,64.77
N$95  (via drill 0.61)
  Top 0.61: RN1.2 68.58,66.04 v68.58,63.5
  Bottom 0.61: v68.58,63.5 81.28,63.5 RD7.K
N$96  (via drill 0.61)
  Top 0.61: SV18.1 25.4,66.04 RD0.A | v17.78,91.44 10.16,85.09 v10.16,69.85
  Bottom 0.61: ZX1.19 24.13,91.44 v17.78,91.44 | v10.16,69.85 10.16,62.23 RD0.A
N$97  (via drill 0.61)
  Top 0.61: SV7.4 62.23,142.24 62.23,134.62 63.5,133.35 v63.5,111.76 | v34.29,110.49 31.75,110.49 31.75,115.57 30.48,116.84 30.48,118.11 S18.3
  Bottom 0.254: S15.3 7.62,119.38 | 15.24,119.38 S16.3 | 30.48,119.38 S18.3
  Bottom 0.559: 13.97,120.65 22.86,120.65 29.21,120.65
  Bottom 0.61: 7.62,119.38 8.89,120.65 13.97,120.65 15.24,119.38 | v63.5,111.76 54.61,111.76 46.99,110.49 v34.29,110.49 | 29.21,120.65 30.48,119.38 | 22.86,120.65 S17.3
N$98  (via drill 0.61)
  Top 0.61: v33.02,64.77 RD1.A | v17.78,86.36 12.7,81.28 v12.7,64.77
  Bottom 0.61: 26.67,64.77 v33.02,64.77 | 26.67,64.77 SV18.2 | ZX1.20 21.59,86.36 v17.78,86.36 | v12.7,64.77 26.67,64.77
N$99  (via drill 0.61)
  Top 0.61: SV18.3 v29.21,63.5
  Bottom 0.406: SV18.3 26.67,69.85 17.78,69.85 17.78,73.66 ZX1.21
  Bottom 0.61: RD2.A 40.64,62.23 38.1,63.5 v29.21,63.5
N$100  (via drill 0.61)
  Top 0.61: v27.94,69.85 ZX1.22
  Bottom 0.406: 38.1,64.77 34.29,64.77 SV18.4 29.21,69.85 v27.94,69.85
  Bottom 0.61: 38.1,64.77 40.64,63.5 48.26,63.5 RD3.A
N$101  (via drill 0.61)
  Top 0.61: RD4.A 60.96,58.42 60.96,41.91 59.69,40.64 v59.69,35.56 | v50.8,35.56 48.26,35.56 48.26,49.53 50.8,50.8 v50.8,52.07 | v30.48,50.8 31.75,50.8 31.75,57.15 34.29,58.42 SV18.5 34.29,71.12 ZX1.27
  Bottom 0.406: v50.8,52.07 39.37,52.07 36.83,50.8 v30.48,50.8
  Bottom 0.61: v50.8,35.56 v59.69,35.56
N$102  (via drill 0.61)
  Top 0.61: SV18.6 36.83,71.12 ZX1.28 39.37,76.2 v41.91,78.74 | RD5.A 63.5,63.5 v63.5,78.74
  Bottom 0.61: v41.91,78.74 v63.5,78.74
N$103  (via drill 0.61)
  Top 0.61: SV18.7 39.37,71.12 ZX1.29 | RD6.A 71.12,60.96 71.12,38.1 69.85,36.83 v69.85,35.56 | v64.77,71.12 66.04,72.39 v66.04,81.28 | v72.39,81.28 74.93,81.28 74.93,68.58 76.2,67.31 v76.2,60.96
  Bottom 0.61: v69.85,35.56 72.39,35.56 SV11.3 | ZX1.29 41.91,71.12 v64.77,71.12 | v66.04,81.28 v72.39,81.28 | v76.2,60.96 73.66,60.96 RD6.A
N$104  (via drill 0.61)
  Top 0.61: SV18.8 44.45,69.85 ZX1.30 | v34.29,76.2 33.02,74.93 33.02,66.04 31.75,64.77 v31.75,58.42 | v16.51,57.15 16.51,39.37 13.97,36.83 13.97,24.13 11.43,21.59 v11.43,6.35 | v96.52,6.35 96.52,63.5 SV12.3
  Bottom 0.61: RD7.A 80.01,60.96 88.9,60.96 95.25,63.5 SV12.3 | ZX1.30 41.91,76.2 v34.29,76.2 | v31.75,58.42 30.48,57.15 v16.51,57.15 | v11.43,6.35 12.7,1.27 90.17,1.27 91.44,5.08 96.52,5.08 v96.52,6.35
N$105  (via drill 0.61)
  Top 0.61: v80.01,38.1 RN2.7 | v44.45,50.8 RB5.K
  Bottom 0.406: v80.01,38.1 72.39,38.1 68.58,41.91 67.31,40.64 66.04,41.91 64.77,40.64 63.5,41.91 63.5,46.99 55.88,46.99 53.34,49.53 46.99,49.53 45.72,50.8 v44.45,50.8
N$106  (via drill 0.61)
  Top 0.61: v58.42,57.15 v58.42,50.8
  Bottom 0.61: RB4.K 54.61,55.88 55.88,57.15 v58.42,57.15 | v58.42,50.8 59.69,49.53 72.39,49.53 73.66,50.8 82.55,50.8 83.82,49.53 83.82,44.45 RN2.6
N$107  (via drill 0.61)
  Top 0.61: v85.09,50.8 RN2.5
  Bottom 0.61: RB3.K 62.23,54.61 68.58,54.61 69.85,53.34 82.55,53.34 v85.09,50.8
N$108  (via drill 0.61)
  Top 0.61: RB2.K 69.85,55.88 v69.85,52.07
  Bottom 0.406: v69.85,52.07 82.55,52.07 87.63,46.99 RN2.4
N$109  (via drill 0.61)
  Top 0.61: v90.17,57.15 RN2.3
  Bottom 0.61: RB1.K 76.2,57.15 v90.17,57.15
N$110  (via drill 0.61)
  Top 0.61: RN2.2 v92.71,55.88
  Bottom 0.61: v92.71,55.88 RB0.K
N$111  (via drill 0.61)
  Top 0.61: RB7.A 26.67,54.61 SV17.8 | v76.2,76.2 81.28,76.2 81.28,83.82 78.74,86.36 78.74,101.6 v74.93,104.14 | v16.51,19.05 v16.51,38.1 | v33.02,17.78 33.02,6.35 36.83,2.54 68.58,2.54 v68.58,7.62 | v72.39,11.43 v72.39,22.86 | v90.17,30.48 91.44,31.75 91.44,60.96 87.63,64.77 87.63,72.39 v86.36,72.39
  Top 1.016: S26.1 S12.8
  Bottom 0.406: v68.58,7.62 v72.39,11.43
  Bottom 0.61: ZX1.40 72.39,76.2 v76.2,76.2 82.55,76.2 v86.36,72.39 | v74.93,104.14 73.66,102.87 68.58,102.87 S26.1 | SV17.8 25.4,41.91 16.51,41.91 v16.51,38.1 | v16.51,19.05 17.78,17.78 v33.02,17.78 | v72.39,22.86 73.66,24.13 82.55,24.13 88.9,30.48 v90.17,30.48
N$112  (via drill 0.61)
  Top 0.406: 30.48,35.56 29.21,36.83
  Top 0.508: 68.58,86.36 68.58,91.44
  Top 0.61: RB6.A 33.02,50.8 29.21,46.99 SV17.7 29.21,36.83 | 69.85,80.01 69.85,85.09 68.58,86.36 | 69.85,80.01 v69.85,76.2 | 68.58,91.44 69.85,91.44 69.85,99.06 S26.2 | v30.48,15.24 30.48,35.56 | v71.12,11.43 71.12,35.56 73.66,38.1 73.66,80.01 69.85,80.01
  Top 1.016: S26.2 S12.7
  Bottom 0.61: v69.85,76.2 67.31,76.2 ZX1.39 | v30.48,15.24 30.48,10.16 35.56,10.16 38.1,7.62 66.04,7.62 v71.12,11.43
N$113
  Top 1.016: 8.89,26.67 8.89,31.75 7.62,31.75
N$114  (via drill 0.61)
  Top 0.508: 66.04,83.82 66.04,97.79
  Top 0.61: SV17.5 34.29,49.53 36.83,54.61 v36.83,57.15 | v49.53,58.42 RB4.A | 66.04,83.82 68.58,83.82 68.58,71.12 v69.85,71.12 71.12,71.12 71.12,63.5 v68.58,60.96 | 66.04,97.79 S26.4
  Top 1.016: S26.4 S12.5
  Bottom 0.61: v36.83,57.15 38.1,58.42 v49.53,58.42 54.61,58.42 55.88,59.69 60.96,59.69 62.23,60.96 v68.58,60.96 | SV14.1 87.63,71.12 v69.85,71.12
N$115  (via drill 0.61)
  Top 0.559: 58.42,87.63 58.42,92.71
  Top 0.61: RB3.A 55.88,57.15 v55.88,60.96 | v62.23,64.77 60.96,66.04 60.96,72.39 ZX1.36 59.69,80.01 v63.5,80.01 | JP4.2 73.66,87.63 v73.66,82.55 | SV17.4 39.37,40.64 45.72,40.64 v45.72,82.55 | 58.42,87.63 57.15,86.36 v57.15,82.55 v57.15,80.01 | 58.42,92.71 55.88,95.25 55.88,102.87 S26.5
  Top 1.016: S26.5 S12.4
  Bottom 0.61: v55.88,60.96 60.96,60.96 62.23,62.23 v62.23,64.77 | v73.66,82.55 73.66,80.01 v63.5,80.01 v57.15,80.01 | v45.72,82.55 v57.15,82.55
N$116  (via drill 0.61)
  Top 0.559: 48.26,90.17 48.26,86.36 50.8,83.82
  Top 0.61: SV17.3 38.1,44.45 38.1,58.42 40.64,60.96 v40.64,64.77 | v53.34,64.77 v55.88,64.77 55.88,72.39 ZX1.35 57.15,74.93 v55.88,76.2 | RB2.A 64.77,59.69 v60.96,63.5 | v44.45,99.06 45.72,97.79 45.72,92.71 48.26,90.17 | v50.8,76.2 50.8,83.82
  Top 1.016: S26.6 S12.3
  Bottom 0.406: S26.6 52.07,101.6 46.99,101.6 v44.45,99.06
  Bottom 0.61: v60.96,63.5 59.69,64.77 v55.88,64.77 | v55.88,76.2 v50.8,76.2
  Bottom 0.813: v40.64,64.77 v53.34,64.77
N$117  (via drill 0.61)
  Top 0.254: 52.07,102.87 S26.7
  Top 0.559: 54.61,83.82 50.8,87.63 50.8,101.6
  Top 0.61: ZX1.34 54.61,83.82 | 50.8,101.6 52.07,102.87 | v66.04,36.83 67.31,38.1 67.31,40.64 68.58,41.91 68.58,52.07 66.04,54.61 v66.04,57.15 v66.04,71.12 | v81.28,116.84 80.01,115.57 80.01,95.25 85.09,95.25 85.09,66.04 87.63,63.5 87.63,48.26 88.9,46.99 v88.9,36.83
  Top 1.016: S26.7 S12.2
  Bottom 0.508: ZX1.34 57.15,76.2 66.04,76.2 v66.04,71.12
  Bottom 0.61: SV17.2 48.26,36.83 v66.04,36.83 v88.9,36.83 | v66.04,57.15 71.12,57.15 RB1.A
  Bottom 0.813: S24.3 130.81,119.38 125.73,115.57 114.3,115.57 114.3,123.19 87.63,123.19 87.63,116.84 v81.28,116.84
N$118  (via drill 0.61)
  Top 0.559: 30.48,80.01 30.48,90.17
  Top 0.61: SV17.1 43.18,44.45 43.18,63.5 40.64,66.04 40.64,69.85 43.18,72.39 v43.18,77.47 43.18,80.01 40.64,80.01 39.37,78.74 30.48,78.74 30.48,80.01 | v52.07,77.47 ZX1.33 52.07,71.12 v53.34,69.85 | RB0.A 77.47,58.42 v77.47,68.58 82.55,73.66 v82.55,85.09 | v40.64,99.06 39.37,97.79 v39.37,91.44 | 30.48,90.17 v30.48,91.44
  Top 0.813: S24.4 121.92,115.57 v121.92,91.44
  Top 1.016: S26.8 S12.1
  Bottom 0.406: S26.8 48.26,102.87 46.99,102.87 43.18,99.06 v40.64,99.06
  Bottom 0.61: v43.18,77.47 v52.07,77.47 | v77.47,68.58 77.47,69.85 v53.34,69.85 | v121.92,91.44 118.11,85.09 v82.55,85.09 | v30.48,91.44 v39.37,91.44
N$119
  Bottom 0.61: RN3.3 68.58,46.99 73.66,46.99 RC6.K
N$120
  Bottom 0.61: RN3.2 69.85,45.72 73.66,45.72 74.93,46.99 81.28,46.99 RC7.K
N$121  (via drill 0.61)
  Top 0.559: 22.86,52.07 22.86,74.93
  Top 0.61: SV22.1 25.4,40.64 RC0.A 22.86,52.07 | v26.67,86.36 26.67,78.74 22.86,74.93
  Bottom 0.61: ZX1.15 31.75,86.36 v26.67,86.36
N$122  (via drill 0.61)
  Top 0.559: 30.48,68.58 27.94,71.12
  Top 0.61: RC1.A 30.48,45.72 SV22.2 | v31.75,80.01 ZX1.16 | 27.94,71.12 v27.94,80.01 | v30.48,52.07 30.48,68.58
  Bottom 0.61: v27.94,80.01 v31.75,80.01 | v30.48,52.07 29.21,52.07 29.21,48.26 RC1.A
N$123  (via drill 0.61)
  Top 0.61: SV22.3 33.02,39.37 35.56,41.91 35.56,44.45 v36.83,45.72 v36.83,52.07 | ZX1.17 29.21,77.47 30.48,76.2 v30.48,69.85 | v35.56,69.85 35.56,64.77 36.83,63.5 36.83,58.42 34.29,57.15 v34.29,52.07
  Bottom 0.406: RC2.A 39.37,48.26 v36.83,45.72
  Bottom 0.61: v35.56,69.85 v30.48,69.85 | v36.83,52.07 v34.29,52.07
N$124  (via drill 0.61)
  Top 0.508: 25.4,80.01 25.4,87.63
  Top 0.559: 20.32,74.93 25.4,80.01
  Top 0.61: 25.4,87.63 ZX1.18 | v20.32,49.53 20.32,74.93 | v33.02,45.72 33.02,40.64 31.75,39.37 31.75,36.83 33.02,35.56 35.56,35.56 SV22.4
  Bottom 0.406: RC3.A 46.99,48.26 45.72,49.53 43.18,49.53 43.18,46.99 40.64,46.99 38.1,44.45 38.1,38.1 SV22.4
  Bottom 0.61: v20.32,49.53 22.86,49.53 24.13,45.72 v33.02,45.72
N$125  (via drill 0.61)
  Top 0.61: RC4.A 57.15,52.07 v55.88,53.34 | v10.16,52.07 10.16,66.04 SV23.1
  Bottom 0.61: v55.88,53.34 24.13,53.34 22.86,52.07 v10.16,52.07 | ZX1.23 26.67,76.2 17.78,76.2 SV23.1
N$126  (via drill 0.61)
  Top 0.61: RC5.A 64.77,52.07 v63.5,52.07 | v15.24,54.61 13.97,55.88 SV23.2 v13.97,77.47
  Bottom 0.61: v63.5,52.07 60.96,53.34 59.69,53.34 55.88,54.61 v15.24,54.61 | ZX1.24 29.21,77.47 v13.97,77.47
N$127  (via drill 0.61)
  Top 0.508: v49.53,76.2 50.8,74.93
  Top 0.559: 16.51,72.39 21.59,77.47 v21.59,78.74
  Top 0.61: v78.74,49.53 SV11.1 | v31.75,77.47 ZX1.25 | SV23.3 16.51,72.39 | v72.39,50.8 RC6.A | v52.07,52.07 52.07,53.34 50.8,54.61 50.8,58.42 53.34,60.96 53.34,63.5 50.8,66.04 50.8,74.93
  Bottom 0.406: v49.53,76.2 43.18,76.2 39.37,78.74
  Bottom 0.61: RC6.A 73.66,49.53 v78.74,49.53 | 31.75,78.74 v31.75,77.47 | v21.59,78.74 31.75,78.74 | v72.39,50.8 60.96,50.8 59.69,52.07 v52.07,52.07 | 31.75,78.74 39.37,78.74
N$128  (via drill 0.61)
  Top 0.61: v19.05,71.12 SV23.4 17.78,66.04 17.78,33.02 19.05,31.75 19.05,16.51 22.86,16.51 v22.86,5.08 | 81.28,49.53 83.82,52.07 v83.82,63.5 | 81.28,49.53 RC7.A | v78.74,7.62 81.28,7.62 81.28,49.53
  Bottom 0.61: ZX1.26 34.29,71.12 v19.05,71.12 | v83.82,63.5 85.09,64.77 SV12.1 | v22.86,5.08 76.2,5.08 v78.74,7.62
N$129  (via drill 0.61)
  Top 0.61: v85.09,39.37 88.9,34.29 88.9,26.67 S13.5
  Bottom 0.61: RN3.1 73.66,39.37 v85.09,39.37
N$130
  Bottom 0.406: IC2.2 50.8,21.59 C6.+
N$131  (via drill 0.61)
  Top 0.61: IC2.1 49.53,20.32 v49.53,24.13
  Bottom 0.61: v49.53,24.13 C5.+
N$132
  Bottom 0.406: IC2.3 52.07,22.86 44.45,22.86 44.45,26.67 C5.-
N$133  (via drill 0.61)
  Top 0.61: IC2.6 v63.5,22.86
  Bottom 0.61: v63.5,22.86 69.85,22.86 C7.-
N$134
  Bottom 0.406: IC2.4 60.96,21.59 71.12,21.59 C8.+
N$135  (via drill 0.61)
  Top 0.61: v60.96,15.24 IC2.5
  Bottom 0.406: v60.96,15.24 73.66,15.24 77.47,19.05 77.47,21.59 C8.-
N$136  (via drill 0.61)
  Top 0.508: 44.45,27.94 v45.72,29.21
  Top 0.61: v44.45,11.43 44.45,27.94
  Bottom 0.254: 53.34,10.16 X2.7
  Bottom 0.61: IC2.13 55.88,29.21 v45.72,29.21 | v44.45,11.43 45.72,8.89 53.34,8.89 53.34,10.16
N$137  (via drill 0.61)
  Top 0.254: X2.8 50.8,10.16
  Top 0.61: IC2.14 57.15,25.4 v57.15,15.24 | 50.8,10.16 v50.8,15.24
  Bottom 0.61: v50.8,15.24 v57.15,15.24
N$138  (via drill 0.61)
  Top 0.254: 49.53,12.7 X2.4
  Top 0.61: IC2.8 64.77,24.13 60.96,24.13 v60.96,22.86 | v55.88,21.59 54.61,20.32 54.61,15.24 53.34,13.97 53.34,11.43 52.07,11.43 52.07,8.89 49.53,8.89 49.53,12.7
  Bottom 0.61: v60.96,22.86 55.88,22.86 v55.88,21.59
N$139  (via drill 0.61)
  Top 0.61: R33.1 35.56,29.21 v35.56,20.32 | v48.26,17.78 49.53,17.78 52.07,15.24 X2.3
  Bottom 0.61: v35.56,20.32 38.1,17.78 v48.26,17.78
N$140
  Top 0.61: D1.C 41.91,29.21 R34.1 R33.2 41.91,34.29 43.18,35.56 Q6.2
N$141
  Bottom 0.61: DPGD.A 2.54,36.83 2.54,46.99 20.32,46.99 R37.1
N$142  (via drill 0.61)
  Top 0.61: R36.1 R35.1 20.32,41.91 20.32,36.83 24.13,36.83 25.4,35.56 25.4,31.75 v29.21,29.21 | v44.45,30.48 Q6.3
  Bottom 0.61: v44.45,30.48 43.18,29.21 v29.21,29.21
N$143  (via drill 0.61)
  Top 0.61: v22.86,44.45 22.86,39.37 26.67,35.56 Q7.B
  Bottom 0.61: R36.2 12.7,44.45 v22.86,44.45
N$144
  Top 0.61: Q7.C 24.13,39.37 24.13,46.99 R39.1 R38.2
  Bottom 0.61: R37.2 16.51,50.8 R39.1
N$145
  Top 0.61: SV13.3 95.25,81.28 4MHZ.2
  Bottom 1.016: 4MHZ.2 C14.1
N$146
  Bottom 0.406: IC4.3 59.69,27.94 59.69,24.13 66.04,24.13 IC2.9
N$147
  Top 1.016: C10.1 6.35,26.67 6.35,19.05 2.54,19.05 2.54,12.7 C9.+
  Bottom 1.27: +.1 25.4,7.62 20.32,8.89 15.24,8.89 | C9.+ 7.62,8.89 15.24,8.89 | 15.24,8.89 IC5.IN
N$148
  Top 0.61: R39.2 12.7,49.53 ICSP1.1
  Top 0.813: ICSP2.1 ICSP1.1
N$149  (via drill 0.61)
  Top 0.61: 4MHZ.1 93.98,77.47 93.98,76.2 | 93.98,76.2 93.98,69.85 SV14.3 | 93.98,76.2 v91.44,76.2
  Bottom 0.61: v91.44,76.2 C13.1
N$150  (via drill 0.61)
  Top 0.61: IC2.12 62.23,27.94 62.23,38.1 IC4.11 | v92.71,60.96 SV12.2 | v63.5,59.69 62.23,58.42 v62.23,45.72
  Bottom 0.406: v62.23,45.72 60.96,45.72 60.96,41.91 IC4.11
  Bottom 0.61: v92.71,60.96 91.44,59.69 v63.5,59.69
N$151  (via drill 0.6 pad 1.27, 0.61)  (1 unrouted)
  Top 0.61: SV13.1 v90.17,105.41 | v69.85,107.95 68.58,107.95 67.31,109.22 62.23,109.22 S12.6 | v40.64,50.8 41.91,52.07 RB5.A
  Top 1.016: S12.6 S26.3
  Bottom 0.406: SV17.6 35.56,46.99 36.83,46.99 v40.64,50.8 | v88.9,73.66 90.17,73.66 SV13.1 | RB5.A v40.64,55.88
  Bottom 0.559: 87.63,107.95 v69.85,107.95
  Bottom 0.61: v90.17,105.41 87.63,107.95
N$152  (via drill 0.61)
  Top 0.61: DPGC.A 6.35,43.18 v6.35,59.69
  Bottom 0.61: v6.35,59.69 12.7,59.69 15.24,55.88 R40.1
N$153
  Bottom 0.61: DVPP.A 5.08,52.07 6.35,53.34 6.35,58.42 R41.1
N$154  (via drill 0.61)
  Top 0.61: ZX1.37 v62.23,77.47
  Bottom 0.406: v62.23,77.47 63.5,77.47 64.77,78.74 85.09,78.74
  Bottom 0.61: 85.09,78.74 86.36,77.47 93.98,77.47 93.98,68.58 SV14.2
N$155  (via drill 0.61)
  Top 0.61: ZX1.38 v64.77,77.47
  Bottom 0.61: v64.77,77.47 83.82,77.47 86.36,74.93 92.71,74.93 SV13.2
N$156
  Bottom 0.61: D3.A 16.51,21.59 D2.C
N$157  (via drill 0.61)
  Top 0.254: ICSP1.4 20.32,31.75
  Top 0.61: v19.05,58.42 19.05,33.02 20.32,31.75 | IC4.2 46.99,25.4 v46.99,20.32 | v24.13,24.13 21.59,24.13 21.59,25.4 ICSP2.4
  Top 0.813: ICSP2.4 ICSP1.4
  Bottom 0.406: v46.99,20.32 43.18,20.32 39.37,24.13 v24.13,24.13
  Bottom 0.61: IC4.2 54.61,34.29 64.77,34.29 IC4.7 | v19.05,58.42 R41.2
N$158  (via drill 0.61)
  Top 0.559: v69.85,2.54 69.85,20.32
  Top 0.61: R40.2 13.97,53.34 v13.97,39.37 | v20.32,35.56 22.86,33.02 ICSP1.5 | IC4.12 63.5,41.91 64.77,40.64 64.77,25.4 69.85,20.32 | v25.4,3.81 24.13,3.81 24.13,8.89 25.4,10.16 25.4,26.67 ICSP2.5
  Top 0.813: ICSP2.5 ICSP1.5
  Bottom 0.61: v13.97,39.37 15.24,35.56 v20.32,35.56 | v69.85,2.54 34.29,2.54 33.02,3.81 v25.4,3.81
N$159
  Top 0.813: ZX1.12 JP5.1
N$160
  Top 0.813: ZX1.11 JP5.2
N$161
  Top 0.61: AN0.2 72.39,5.08 72.39,2.54 77.47,2.54 77.47,11.43 80.01,13.97 SV15.1
N$162  (via drill 0.61)
  Top 0.508: 60.96,13.97 62.23,15.24
  Top 0.61: v68.58,12.7 68.58,16.51 62.23,16.51 62.23,15.24 | 60.96,13.97 60.96,11.43 55.88,6.35 34.29,6.35 34.29,15.24 36.83,17.78 C2.+ | v27.94,20.32 v27.94,26.67
  Top 0.813: ICSP1.2 ICSP2.2 | v120.65,119.38 120.65,86.36 128.27,86.36 128.27,71.12 130.81,69.85 v130.81,33.02
  Bottom 0.559: 120.65,125.73 85.09,125.73
  Bottom 0.61: 27.94,31.75 24.13,31.75 22.86,33.02 17.78,33.02 ICSP1.2 | 27.94,31.75 IC4.1 | R42.1 67.31,135.89 77.47,135.89 77.47,132.08 85.09,125.73 | v120.65,119.38 120.65,125.73 | v130.81,33.02 123.19,25.4 110.49,25.4 97.79,12.7 v68.58,12.7 | v27.94,26.67 27.94,31.75 | v27.94,20.32 27.94,19.05 33.02,19.05 33.02,20.32 34.29,21.59 C2.+
N$163
  Top 0.61: AN1.2 82.55,6.35 SV15.2
N$164
  Top 0.61: AN2.2 85.09,7.62 SV15.3
N$165
  Top 0.61: AN3.2 87.63,7.62 SV15.4
N$166
  Top 0.406: AN4.2 90.17,10.16
  Top 0.61: 90.17,10.16 SV15.5
N$167  (via drill 0.61)
  Top 0.406: 92.71,8.89 v93.98,7.62
  Top 0.61: 92.71,8.89 SV15.6
  Bottom 0.61: AN5.2 97.79,7.62 v93.98,7.62
N$168
  Top 0.61: AN6.2 101.6,6.35 101.6,1.27 95.25,1.27 SV15.7
N$169
  Top 0.61: AN7.2 106.68,6.35 106.68,7.62 101.6,7.62 101.6,8.89 97.79,13.97 SV15.8
N$170  (via drill 0.61)
  Top 0.61: SV16.6 31.75,100.33 v31.75,93.98
  Bottom 0.61: ZX1.8 48.26,92.71 33.02,92.71 v31.75,93.98 17.78,93.98 15.24,91.44 3.81,91.44 3.81,77.47 SV24.3
N$171  (via drill 0.61)
  Top 0.406: v22.86,104.14 SV16.8
  Top 0.61: v6.35,104.14 1.27,104.14 1.27,71.12 v2.54,71.12
  Bottom 0.61: v6.35,104.14 v22.86,104.14 | v2.54,71.12 7.62,71.12 SV6.3
N$172  (via drill 0.61)
  Top 0.559: v27.94,83.82 SV16.7
  Bottom 0.61: v27.94,83.82 12.7,83.82 SV5.3
N$173  (via drill 0.61)
  Top 0.61: SV25.3 1.27,54.61 1.27,11.43 12.7,1.27 71.12,1.27 71.12,7.62 74.93,7.62 v74.93,15.24
  Bottom 0.508: v74.93,15.24 81.28,21.59 95.25,21.59 101.6,26.67 119.38,26.67 R55.S
N$174
  Top 1.016: SV3.1 S14.1
N$175
  Top 1.016: R56.2 128.27,33.02 JP6.2
N$176
  Bottom 0.61: SV26.5 123.19,5.08 116.84,8.89 116.84,22.86 142.24,22.86 R57.S
N$177
  Top 1.016: SV3.2 S14.2
N$178
  Top 1.016: SV26.18 153.67,7.62 153.67,19.05 R57.E
N$179
  Top 0.508: 88.9,139.7 IC6.6
  Top 0.61: R63.2 88.9,139.7
  Bottom 0.61: S10.1 82.55,135.89 90.17,135.89 R63.2
N$180
  Top 1.016: R58.1 156.21,6.35 SV26.19
N$181
  Bottom 0.61: R58.2 152.4,29.21 148.59,33.02 JP7.1
N$182
  Top 0.813: IC6.11 93.98,142.24 R64.2
  Bottom 0.61: S10.2 83.82,134.62 91.44,134.62 R64.2
N$183
  Top 1.016: SV26.1 SV27.1
N$184
  Top 1.016: SV26.2 SV27.2
N$185
  Bottom 0.61: SV26.6 125.73,5.08 118.11,10.16 SV27.3
N$186
  Bottom 0.61: SV26.7 128.27,5.08 120.65,10.16 SV27.4
N$187
  Top 1.016: SV26.8 130.81,7.62 123.19,7.62 SV27.5
N$188
  Bottom 0.813: SV27.6 132.08,7.62 151.13,7.62 SV26.17
N$189
  Top 1.016: SV26.9 SV28.1
N$190
  Top 1.016: SV26.10 SV28.2
N$191
  Top 1.016: SV26.11 SV28.3
N$192
  Top 1.016: SV26.12 SV28.4
N$193
  Top 1.016: SV26.13 SV28.5
N$194
  Top 1.016: SV26.14 SV28.6
N$195
  Top 1.016: SV26.15 SV28.7
N$196
  Top 1.016: SV26.16 SV28.8
N$197  (via drill 0.61)
  Top 0.508: IC6.2 83.82,144.78 81.28,142.24 81.28,139.7 78.74,137.16 v78.74,116.84
  Top 2.54: D8.C D4.A
  Bottom 0.254: 158.75,86.36 X4.1
  Bottom 0.61: v78.74,116.84 80.01,115.57 90.17,115.57 90.17,120.65 97.79,120.65
  Bottom 1.778: D8.C 133.35,86.36 158.75,86.36 162.56,86.36 162.56,99.06 157.48,99.06 149.86,104.14 133.35,104.14 132.08,105.41 119.38,105.41 97.79,120.65
N$198  (via drill 0.61)
  Top 0.61: IC6.3 85.09,144.78 83.82,143.51 83.82,116.84 85.09,115.57 v85.09,113.03
  Top 2.54: D5.A D9.C
  Bottom 0.254: 158.75,91.44 X4.2
  Bottom 1.016: v85.09,113.03 92.71,105.41 102.87,105.41 106.68,97.79 125.73,97.79 D5.A
  Bottom 1.676: 157.48,92.71 158.75,91.44
  Bottom 1.778: 157.48,92.71 133.35,92.71 D9.C
N$199  (via drill 0.61)
  Top 0.813: IC6.13 95.25,142.24 v95.25,119.38
  Top 2.54: D10.C D6.A
  Bottom 0.254: X5.1 158.75,96.52
  Bottom 1.016: D6.A 125.73,100.33
  Bottom 1.27: v95.25,119.38 105.41,111.76 105.41,106.68 113.03,104.14 116.84,100.33 125.73,100.33
  Bottom 1.778: 158.75,96.52 153.67,96.52 148.59,99.06 133.35,99.06 D10.C
N$200  (via drill 0.61)
  Top 1.27: v101.6,121.92 101.6,135.89 102.87,138.43 102.87,152.4 IC6.14
  Top 2.54: D7.A D11.C
  Bottom 0.254: 158.75,101.6 X5.2
  Bottom 1.27: v101.6,121.92 106.68,118.11 115.57,111.76 121.92,107.95 D7.A
  Bottom 1.778: 158.75,101.6 158.75,111.76 134.62,111.76 D11.C
N$201  (via drill 0.61)
  Top 0.61: v114.3,74.93 110.49,78.74 D4.C
  Top 1.118: IC6.4 86.36,154.94 106.68,154.94 106.68,111.76 D7.C
  Top 2.54: D4.C D5.C D6.C D7.C
  Bottom 0.254: 158.75,76.2 X3.1
  Bottom 1.016: 158.75,76.2 157.48,74.93 v114.3,74.93
N$202  (via drill 0.61)
  Top 1.016: IC6.1 72.39,147.32 S9.4 72.39,138.43 v73.66,137.16
  Bottom 0.61: R61.2 R62.2 v73.66,137.16
N$203
  Top 0.61: S9.3 R59.2
  Bottom 0.61: R60.2 95.25,138.43 80.01,138.43 S9.3
  Bottom 0.813: IC6.15 100.33,143.51 R59.2
N$204
  Top 1.016: SV3.3 S14.3
N$205
  Top 1.016: SV3.4 S14.4
N$206
  Top 0.61: JP10.1 S9.1
N$207
  Top 0.61: JP10.2 S9.2
N$208  (via drill 0.61)
  Top 0.508: IC6.12 96.52,149.86 97.79,149.86 | 99.06,111.76 99.06,149.86
  Top 0.559: 99.06,149.86 97.79,149.86
  Top 0.61: v35.56,40.64 36.83,39.37 36.83,24.13 38.1,22.86 38.1,15.24 35.56,12.7 v35.56,7.62 | v101.6,11.43 104.14,13.97 v104.14,52.07 | v102.87,60.96 102.87,109.22 S14.5 99.06,111.76
  Bottom 0.61: v35.56,40.64 R68.2 | v35.56,7.62 36.83,6.35 69.85,6.35 73.66,11.43 v101.6,11.43 | v104.14,52.07 96.52,52.07 96.52,60.96 v102.87,60.96
N$209  (via drill 0.61)
  Top 0.61: S14.6 v97.79,144.78
  Bottom 0.457: 93.98,144.78 IC6.10
  Bottom 0.508: v97.79,144.78 93.98,144.78
  Bottom 0.61: R67.2 90.17,113.03 95.25,113.03 S14.6
N$210  (via drill 0.61)
  Top 0.61: S14.7 95.25,107.95 92.71,107.95 R66.2 86.36,121.92 85.09,123.19 v85.09,142.24 | v90.17,142.24 IC6.7
  Bottom 0.813: v85.09,142.24 v90.17,142.24
N$211
  Top 0.61: S14.8 R65.2 87.63,119.38 IC6.5
N$212
  Top 0.813: S24.2 134.62,118.11 IC7.3
N$213
  Top 0.813: IC7.8 124.46,134.62 124.46,148.59
  Top 1.27: R76.1 124.46,148.59 R75.1 Q11.C
  Top 1.778: Q9.C 146.05,134.62 D12.C
  Bottom 1.27: 158.75,115.57 137.16,115.57 137.16,124.46 128.27,124.46 125.73,123.19 124.46,130.81 | 124.46,130.81 129.54,132.08 | 129.54,132.08 IC7.8 | D13.C 114.3,130.81 124.46,130.81 | D12.C 143.51,132.08 129.54,132.08
  Bottom 1.778: 158.75,115.57 X7.1
N$214
  Top 0.813: S24.1 133.35,119.38 133.35,128.27 137.16,132.08 IC7.5
N$215
  Top 1.676: D12.A 143.51,124.46 149.86,124.46 | 149.86,124.46 D14.C | 149.86,124.46 162.56,124.46 162.56,154.94 148.59,154.94
  Top 1.778: 148.59,154.94 Q9.E
  Bottom 0.254: 158.75,132.08 X6.1
  Bottom 1.676: Q10.C 134.62,154.94 148.59,154.94 Q9.E
  Bottom 1.778: 158.75,132.08 149.86,132.08 D14.C
N$216
  Top 1.778: Q12.C 111.76,142.24 116.84,135.89 D15.C 116.84,125.73 D13.A
  Bottom 1.676: 125.73,154.94 Q11.E | 125.73,154.94 111.76,154.94 Q12.C | 125.73,154.94 129.54,154.94 129.54,144.78
  Bottom 1.778: 129.54,144.78 158.75,144.78 X6.2
N$217
  Top 1.27: R69.2 Q9.B
N$218
  Top 1.016: R70.2 Q10.B
N$219
  Top 1.016: R71.1 Q11.B
N$220
  Top 1.27: R72.1 Q12.B
N$221  (via drill 0.6)
  Top 0.813: v135.89,142.24 135.89,148.59 R73.1
  Bottom 0.813: v135.89,142.24 INDIETRO.A
N$222
  Top 1.27: R74.2 R69.1
  Bottom 0.813: R72.2 118.11,138.43 119.38,137.16 140.97,137.16 R74.2
  Bottom 1.016: IC7.1 133.35,129.54 146.05,129.54 146.05,138.43 R69.1
N$223
  Bottom 0.813: R74.1 140.97,149.86 148.59,149.86 AVANTI.A
N$224
  Top 1.016: IC7.7 R70.1 R73.2
  Bottom 0.813: R71.2 120.65,139.7 132.08,139.7 R70.1
N$225
  Top 1.016: S25.1 SV21.4
N$226
  Top 0.61: IC7.2 132.08,129.54 135.89,133.35 135.89,139.7 125.73,139.7 R76.2
  Top 1.016: R78.2 R76.2
N$227
  Top 0.813: IC7.6 132.08,132.08 123.19,132.08 R77.2
  Top 1.016: R77.2 R75.2
N$228
  Top 1.016: S25.2 SV21.3
N$229
  Top 1.016: S25.3 SV21.2
N$230
  Top 1.016: S25.4 SV21.1
N$231
  Bottom 0.254: 15.24,5.08 X1.1
  Bottom 1.016: ~.1 16.51,2.54 15.24,5.08
N$232
  Bottom 0.254: X1.2 20.32,5.08
  Bottom 0.61: ~-.1 30.48,6.35 20.32,6.35 20.32,5.08
N$233  (via drill 0.61, 1 pad 1.78)
  Top 0.61: v68.58,92.71 v67.31,93.98 | v91.44,88.9 96.52,83.82 v96.52,74.93 | v106.68,62.23 106.68,58.42 105.41,57.15 105.41,30.48 R10.1
  Bottom 0.61: v67.31,93.98 57.15,93.98 S26.12 | v68.58,92.71 87.63,92.71 v91.44,88.9 | 97.79,62.23 97.79,74.93 v96.52,74.93 | v106.68,62.23 97.79,62.23 | 97.79,62.23 95.25,62.23 95.25,48.26 97.79,48.26 SV20.4
  Bottom 0.813: R10.1 101.6,29.21 v101.6,30.48
N$234  (via drill 0.61)
  Top 0.559: 86.36,63.5 83.82,66.04
  Top 0.61: 83.82,66.04 v83.82,93.98 | v86.36,54.61 86.36,63.5
  Bottom 0.406: 68.58,93.98 67.31,92.71
  Bottom 0.61: S26.11 54.61,92.71 67.31,92.71 | v83.82,93.98 68.58,93.98 | v86.36,54.61 92.71,54.61 92.71,46.99 96.52,46.99 97.79,43.18 SV20.3
  Bottom 0.813: SV20.3 R9.2

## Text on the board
Bottom: G-Tronic Robotics | Micro-GT PIC versatile IDE | G-Tronic Robotics | maggio 2010
tNames: UP/DOWN | UP/DOWN | UP/DOWN | UP/DOWN | 14 | 2 | 1 | 15 | reset | 16F84 | abilita | sensori extracorrente | abilita L298 | analogici extracorrente | Vcc Mot | collega ingressi a PORTA | collega ingressi a PORTB | pulsanti diretti B | enable H bridge | pulsanti diretti A | abilita stepper signals | D | Clock 16F877 | DIRECT ANALOG/PORT A (40p) | vdd | RC2/876 | RC0 | alimenta 16F84 | C | RC3/876 | vss | RC1 | collega stepper signals | abilita display 7 seg | G-Tronic | B | Robotics | 18pF | 18pF | A | 20Mhz | Clock 16F84 | gnd | RS/RW/EN | 22pF | Vcc | passo/passo | Clock 16F84 | DIRECT PORT D | direct control RC4-RC7 | RS232 | CONTRASTO LCD | BCD | DIRECT PORT B | RS232 | DIRECT RC0-RC3 | RB | RC | RD | catodi | catodo | anodo | back light LCD | abilita GLCD | OUT | punti decimali | ENABLE | contrasto LCD | canali analogici | collegare RB0 to RB5 | 7812 | 7805 | contrasto GLCD | collegare RD0 to RD7 | Micro-GT PIC | connessione diretta display GLCD | versatile I.D.E.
